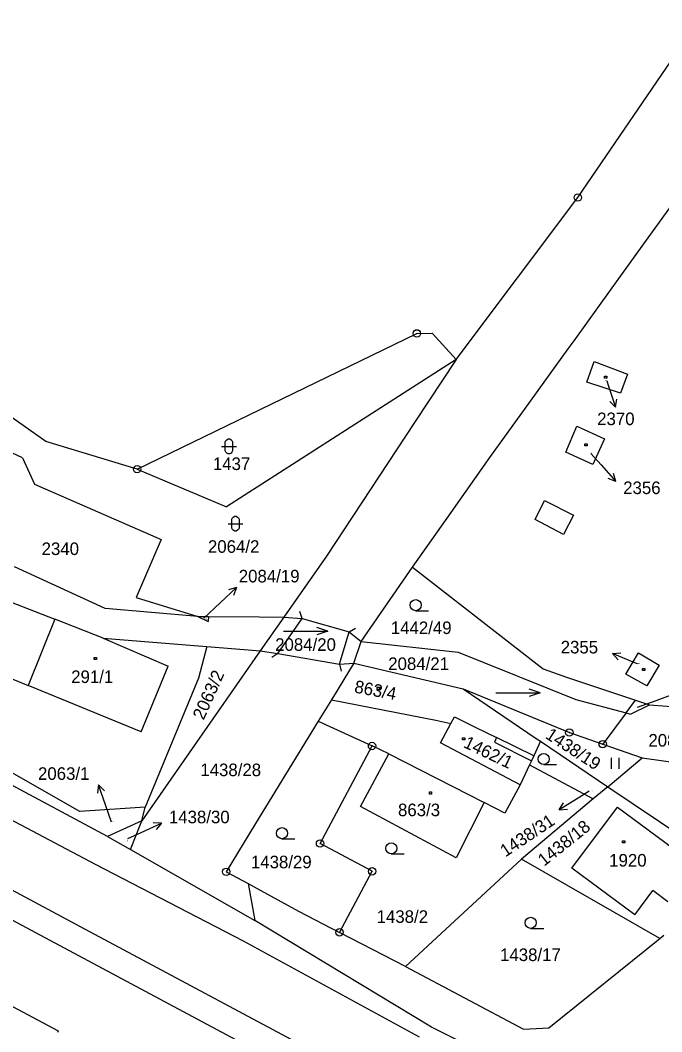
# Model space of a CAD drawing. Extents: x -795483 to -789093, y -1112258 to -1108741.
# Drawn here: x -792952.2 to -792865.5, y -1110319.8 to -1110183.1 of the extents above; entities that cross this region are included whole.
import ezdxf

# ---------------------------------------------------------------- set-up
doc = ezdxf.new("R2010")
doc.units = 0
for name, color, linetype in [('Komunikace', 7, 'Continuous'), ('Popis vodovodních řadů', 7, 'Continuous'), ('Vrstva 1', 7, 'Continuous'), ('Vrstva 14', 7, 'Continuous'), ('Vrstva 15', 7, 'Continuous'), ('Vrstva 16', 7, 'Continuous'), ('Vrstva 2', 7, 'Continuous'), ('Vrstva 23', 7, 'Continuous'), ('Vrstva 25', 7, 'Continuous'), ('Vrstva 28', 7, 'Continuous')]:
    doc.layers.add(name, color=color, linetype=linetype)

msp = doc.modelspace()

# ---------------------------------------------------------------- linework, layer by layer
at = {"layer": 'Komunikace'}
for p, q in [((-792872.92, -1110231.83), (-792872.68, -1110232.55)), ((-792875.08, -1110241.63), (-792873.69, -1110243.19)), ((-792927.41, -1110263.89), (-792925.18, -1110261.82)), ((-792868.75, -1110270.08), (-792869.36, -1110269.83)), ((-792868.77, -1110275.95), (-792866.25, -1110275.03)), ((-792875.31, -1110287.31), (-792876.79, -1110288.23)), ((-792939.88, -1110291.47), (-792940.65, -1110289.28)), ((-792937.68, -1110293.68), (-792935.87, -1110292.86))]:
    msp.add_line(p, q, dxfattribs=at)
at = {"layer": 'Popis vodovodních řadů'}
for p, q in [((-792914.11, -1110263.94), (-792914.42, -1110263)), ((-792907.75, -1110265.75), (-792906.88, -1110265.27)), ((-792917.38, -1110268.7), (-792918.22, -1110269.22)), ((-792909.08, -1110270.11), (-792908.84, -1110271.07))]:
    msp.add_line(p, q, dxfattribs=at)
at = {"layer": 'Vrstva 1'}
for p, q in [((-792876.83, -1110207.04), (-792860.5, -1110183.08)), ((-792867.33, -1110212.5), (-792861.96, -1110205.07)), ((-792893.29, -1110228.94), (-792876.83, -1110207.04)), ((-792872.43, -1110219.57), (-792867.33, -1110212.5)), ((-792877.35, -1110226.4), (-792872.43, -1110219.57)), ((-792936.43, -1110243.76), (-792898.61, -1110225.41)), ((-792898.61, -1110225.41), (-792896.52, -1110225.36)), ((-792896.52, -1110225.36), (-792893.29, -1110228.94)), ((-792878.15, -1110227.5), (-792877.35, -1110226.4)), ((-792883.23, -1110234.55), (-792878.15, -1110227.5)), ((-792893.29, -1110228.94), (-792924.34, -1110248.84)), ((-792893.29, -1110228.94), (-792898.91, -1110237.46)), ((-792875.6, -1110231.99), (-792874.62, -1110229.22)), ((-792874.62, -1110229.22), (-792870.1, -1110230.91)), ((-792870.1, -1110230.91), (-792871.07, -1110233.51)), ((-792871.07, -1110233.51), (-792875.6, -1110231.99)), ((-792888.74, -1110242.19), (-792883.23, -1110234.55)), ((-792898.91, -1110237.46), (-792910.83, -1110255.53)), ((-792878.45, -1110241.45), (-792876.98, -1110237.97)), ((-792876.98, -1110237.97), (-792873.23, -1110239.68)), ((-792951.92, -1110242.23), (-792956.62, -1110240.06)), ((-792873.23, -1110239.68), (-792874.8, -1110243.12)), ((-792874.8, -1110243.12), (-792878.45, -1110241.45)), ((-792951.92, -1110242.23), (-792950.31, -1110245.78)), ((-792893.98, -1110249.64), (-792888.74, -1110242.19)), ((-792936.43, -1110243.76), (-792924.34, -1110248.84)), ((-792950.31, -1110245.78), (-792933.18, -1110253.25)), ((-792899.17, -1110257.02), (-792893.98, -1110249.64)), ((-792933.18, -1110253.25), (-792936.55, -1110261.13)), ((-792910.83, -1110255.53), (-792916.57, -1110263.77)), ((-792940.73, -1110262.6), (-792953.02, -1110256.95)), ((-792906.12, -1110267.05), (-792899.17, -1110257.02)), ((-792899.17, -1110257.02), (-792881.53, -1110270.73)), ((-792958.2, -1110259.87), (-792947.55, -1110264.05)), ((-792936.55, -1110261.13), (-792928.23, -1110263.66)), ((-792928.23, -1110263.66), (-792940.73, -1110262.6)), ((-792928.23, -1110263.66), (-792926.8, -1110264.36)), ((-792928.23, -1110263.66), (-792926.76, -1110263.67)), ((-792926.76, -1110263.67), (-792926.8, -1110264.36)), ((-792926.76, -1110263.67), (-792919.91, -1110263.74)), ((-792919.91, -1110263.74), (-792916.57, -1110263.77)), ((-792916.57, -1110263.77), (-792919.79, -1110268.32)), ((-792916.57, -1110263.77), (-792914.11, -1110263.94)), ((-792914.11, -1110263.94), (-792907.75, -1110265.75)), ((-792947.55, -1110264.05), (-792951.18, -1110272.99)), ((-792941.03, -1110266.61), (-792947.55, -1110264.05)), ((-792941.03, -1110266.61), (-792927.02, -1110267.74)), ((-792907.75, -1110265.75), (-792906.12, -1110267.05)), ((-792927.02, -1110267.74), (-792928.14, -1110272.02)), ((-792927.02, -1110267.74), (-792921.4, -1110268.19)), ((-792907.12, -1110270), (-792906.12, -1110267.05)), ((-792906.12, -1110267.05), (-792893, -1110268.51)), ((-792961.7, -1110268.67), (-792951.18, -1110272.99)), ((-792919.79, -1110268.32), (-792935.78, -1110291.3)), ((-792921.4, -1110268.19), (-792919.79, -1110268.32)), ((-792919.79, -1110268.32), (-792917.38, -1110268.7)), ((-792917.38, -1110268.7), (-792909.08, -1110270.11)), ((-792893, -1110268.51), (-792877.11, -1110274.91)), ((-792870.36, -1110271.49), (-792868.65, -1110268.61)), ((-792868.65, -1110268.61), (-792865.84, -1110270.25)), ((-792909.08, -1110270.11), (-792907.12, -1110270)), ((-792907.12, -1110270), (-792907.69, -1110270.93)), ((-792907.12, -1110270), (-792892.36, -1110273.46)), ((-792881.53, -1110270.73), (-792878.38, -1110271.88)), ((-792865.84, -1110270.25), (-792867.49, -1110273.06)), ((-792928.14, -1110272.02), (-792935.32, -1110289.46)), ((-792907.69, -1110270.93), (-792910.16, -1110274.96)), ((-792878.38, -1110271.88), (-792869.04, -1110275)), ((-792867.49, -1110273.06), (-792870.36, -1110271.49)), ((-792892.36, -1110273.46), (-792877.98, -1110279.37)), ((-792892.36, -1110273.46), (-792882.45, -1110280.15)), ((-792877.11, -1110274.91), (-792870.31, -1110276.7)), ((-792944.19, -1110290.03), (-792968.57, -1110276.11)), ((-792910.16, -1110274.96), (-792911.93, -1110277.84)), ((-792910.16, -1110274.96), (-792896.04, -1110277.71)), ((-792870.31, -1110276.7), (-792869.04, -1110275)), ((-792869.7, -1110276.86), (-792867.13, -1110275.64)), ((-792869.04, -1110275), (-792867.13, -1110275.64)), ((-792867.13, -1110275.64), (-792832.52, -1110277.99)), ((-792894.02, -1110278.16), (-792893.53, -1110277.23)), ((-792893.53, -1110277.23), (-792890.72, -1110278.62)), ((-792870.31, -1110276.7), (-792873.47, -1110280.93)), ((-792870.31, -1110276.7), (-792869.7, -1110276.86)), ((-792940.44, -1110293.43), (-792969.24, -1110277.99)), ((-792911.93, -1110277.84), (-792920.4, -1110291.66)), ((-792911.93, -1110277.84), (-792904.66, -1110281.18)), ((-792896.04, -1110277.71), (-792894.02, -1110278.16)), ((-792895.4, -1110280.77), (-792894.02, -1110278.16)), ((-792890.72, -1110278.62), (-792887.81, -1110280.05)), ((-792882.78, -1110282.53), (-792887.81, -1110280.05)), ((-792882.45, -1110280.15), (-792881.86, -1110280.55)), ((-792877.98, -1110279.37), (-792873.47, -1110280.93)), ((-792911.69, -1110294.36), (-792904.66, -1110281.18)), ((-792902.39, -1110282.23), (-792904.66, -1110281.18)), ((-792884.61, -1110286.45), (-792895.4, -1110280.77)), ((-792881.86, -1110280.55), (-792882.78, -1110282.53)), ((-792881.86, -1110280.55), (-792872.78, -1110286.68)), ((-792873.47, -1110280.93), (-792868.13, -1110282.78)), ((-792906.21, -1110289.36), (-792902.39, -1110282.23)), ((-792882.78, -1110282.53), (-792883.08, -1110283.17)), ((-792872.78, -1110286.68), (-792868.13, -1110282.78)), ((-792868.13, -1110282.78), (-792858.5, -1110284.12)), ((-792883.35, -1110283.75), (-792884.61, -1110286.45)), ((-792883.08, -1110283.17), (-792883.35, -1110283.75)), ((-792883.35, -1110283.75), (-792874.76, -1110288.34)), ((-792987.4, -1110286.52), (-792903.63, -1110331.24)), ((-792884.61, -1110286.45), (-792886.72, -1110290.26)), ((-792872.78, -1110286.68), (-792874.76, -1110288.34)), ((-792872.78, -1110286.68), (-792855.41, -1110298.4)), ((-792874.76, -1110288.34), (-792884.46, -1110296.46)), ((-792935.32, -1110289.46), (-792944.19, -1110290.03)), ((-792935.78, -1110291.3), (-792935.32, -1110289.46)), ((-792896.99, -1110294.3), (-792906.21, -1110289.36)), ((-792889.5, -1110288.84), (-792893.29, -1110296.28)), ((-792886.72, -1110290.26), (-792889.5, -1110288.84)), ((-792877.63, -1110297.71), (-792871.48, -1110289.47)), ((-792871.48, -1110289.47), (-792863, -1110295.7)), ((-792935.78, -1110291.3), (-792940.44, -1110293.43)), ((-792937.34, -1110295.19), (-792935.78, -1110291.3)), ((-792920.4, -1110291.66), (-792924.39, -1110298.18)), ((-792940.44, -1110293.43), (-792937.34, -1110295.19)), ((-792937.34, -1110295.19), (-792920.52, -1110304.75)), ((-792904.65, -1110298.12), (-792911.69, -1110294.36)), ((-792893.29, -1110296.28), (-792896.99, -1110294.3)), ((-792884.46, -1110296.46), (-792900.15, -1110310.99)), ((-792865.76, -1110307.22), (-792884.46, -1110296.46)), ((-792924.39, -1110298.18), (-792921.42, -1110299.79)), ((-792909.06, -1110306.37), (-792904.65, -1110298.12)), ((-792869.11, -1110304.01), (-792877.63, -1110297.71)), ((-792987.23, -1110298.41), (-792947.08, -1110319.7)), ((-792921.42, -1110299.79), (-792920.21, -1110300.45)), ((-792921.42, -1110299.79), (-792920.52, -1110304.75)), ((-792920.21, -1110300.45), (-792914.61, -1110303.49)), ((-792869.11, -1110304.01), (-792866.7, -1110300.73)), ((-792864.66, -1110302.23), (-792866.7, -1110300.73)), ((-792914.61, -1110303.49), (-792909.06, -1110306.37)), ((-792896.6, -1110319.19), (-792920.52, -1110304.75)), ((-792900.15, -1110310.99), (-792909.06, -1110306.37)), ((-792880.76, -1110319.28), (-792865.76, -1110307.22)), ((-792865.76, -1110307.22), (-792865.22, -1110306.76)), ((-792900.15, -1110310.99), (-792884.2, -1110319.45)), ((-792947.08, -1110319.7), (-792947.2, -1110319.92)), ((-792892.13, -1110321.45), (-792896.6, -1110319.19)), ((-792884.2, -1110319.45), (-792880.76, -1110319.28))]:
    msp.add_line(p, q, dxfattribs=at)
msp.add_lwpolyline([(-792936.43, -1110243.76), (-792948.79, -1110240.01), (-792954.6, -1110235.91)], dxfattribs=at)
at = {"layer": 'Vrstva 16'}
for p, q in [((-792872.68, -1110232.55), (-792871.73, -1110235.4)), ((-792871.73, -1110235.4), (-792872.52, -1110234.6)), ((-792871.73, -1110235.4), (-792871.57, -1110234.29)), ((-792873.69, -1110243.19), (-792871.7, -1110245.43)), ((-792871.7, -1110245.43), (-792871.99, -1110244.35)), ((-792871.7, -1110245.43), (-792872.73, -1110245.02)), ((-792925.18, -1110261.82), (-792922.98, -1110259.77)), ((-792922.98, -1110259.77), (-792924.06, -1110260.09)), ((-792922.98, -1110259.77), (-792923.38, -1110260.82)), ((-792872.13, -1110268.67), (-792871.01, -1110268.6)), ((-792869.36, -1110269.83), (-792872.13, -1110268.67)), ((-792872.13, -1110268.67), (-792871.4, -1110269.52)), ((-792866.25, -1110275.03), (-792863.43, -1110273.99)), ((-792941.65, -1110286.45), (-792941.79, -1110287.56)), ((-792940.65, -1110289.28), (-792941.65, -1110286.45)), ((-792941.65, -1110286.45), (-792940.84, -1110287.23)), ((-792876.79, -1110288.23), (-792879.34, -1110289.82)), ((-792879.34, -1110289.82), (-792878.75, -1110288.86)), ((-792879.34, -1110289.82), (-792878.22, -1110289.71)), ((-792935.87, -1110292.86), (-792933.13, -1110291.63)), ((-792933.13, -1110291.63), (-792934.25, -1110291.58)), ((-792933.13, -1110291.63), (-792933.84, -1110292.49))]:
    msp.add_line(p, q, dxfattribs=at)
at = {"layer": 'Vrstva 2'}
for p, q in [((-792882.6, -1110250.56), (-792881.34, -1110248.01)), ((-792881.34, -1110248.01), (-792877.43, -1110250)), ((-792877.43, -1110250), (-792878.75, -1110252.61)), ((-792878.75, -1110252.61), (-792882.6, -1110250.56)), ((-792917.38, -1110268.7), (-792914.11, -1110263.94)), ((-792941.03, -1110266.61), (-792932.22, -1110270.38)), ((-792909.08, -1110270.11), (-792907.75, -1110265.75)), ((-792935.89, -1110279.29), (-792932.22, -1110270.38)), ((-792935.89, -1110279.29), (-792951.18, -1110272.99)), ((-792980.05, -1110277.11), (-792942.11, -1110297.14)), ((-792887.81, -1110280.05), (-792888.12, -1110280.67)), ((-792888.12, -1110280.67), (-792883.08, -1110283.17)), ((-792902.39, -1110282.23), (-792889.5, -1110288.84)), ((-792985.44, -1110283.55), (-792944.81, -1110305.21)), ((-792942.11, -1110297.14), (-792922.09, -1110307.54)), ((-792944.81, -1110305.21), (-792903.48, -1110327.29)), ((-792922.09, -1110307.54), (-792898.28, -1110320.5))]:
    msp.add_line(p, q, dxfattribs=at)
at = {"layer": 'Vrstva 23'}
for p, q in [((-792925.01, -1110240.68), (-792923.01, -1110240.68)), ((-792924.51, -1110240.08), (-792924.41, -1110239.88)), ((-792924.51, -1110241.28), (-792924.51, -1110240.08)), ((-792924.41, -1110239.88), (-792924.31, -1110239.78)), ((-792924.31, -1110239.78), (-792924.11, -1110239.68)), ((-792924.11, -1110239.68), (-792923.91, -1110239.68)), ((-792923.91, -1110239.68), (-792923.71, -1110239.78)), ((-792923.71, -1110239.78), (-792923.61, -1110239.88)), ((-792923.61, -1110239.88), (-792923.51, -1110240.08)), ((-792923.51, -1110240.08), (-792923.51, -1110241.28)), ((-792924.41, -1110241.48), (-792924.51, -1110241.28)), ((-792924.31, -1110241.58), (-792924.41, -1110241.48)), ((-792924.11, -1110241.68), (-792924.31, -1110241.58)), ((-792923.91, -1110241.68), (-792924.11, -1110241.68)), ((-792923.71, -1110241.58), (-792923.91, -1110241.68)), ((-792923.61, -1110241.48), (-792923.71, -1110241.58)), ((-792923.51, -1110241.28), (-792923.61, -1110241.48)), ((-792923.63, -1110250.53), (-792923.53, -1110250.33)), ((-792923.53, -1110250.33), (-792923.43, -1110250.23)), ((-792923.43, -1110250.23), (-792923.23, -1110250.13)), ((-792923.23, -1110250.13), (-792923.03, -1110250.13)), ((-792923.03, -1110250.13), (-792922.83, -1110250.23)), ((-792922.83, -1110250.23), (-792922.73, -1110250.33)), ((-792922.73, -1110250.33), (-792922.63, -1110250.53)), ((-792924.13, -1110251.13), (-792922.13, -1110251.13)), ((-792923.63, -1110251.73), (-792923.63, -1110250.53)), ((-792922.63, -1110250.53), (-792922.63, -1110251.73)), ((-792923.53, -1110251.93), (-792923.63, -1110251.73)), ((-792923.43, -1110252.03), (-792923.53, -1110251.93)), ((-792923.23, -1110252.13), (-792923.43, -1110252.03)), ((-792923.03, -1110252.13), (-792923.23, -1110252.13)), ((-792922.83, -1110252.03), (-792923.03, -1110252.13)), ((-792922.73, -1110251.93), (-792922.83, -1110252.03)), ((-792922.63, -1110251.73), (-792922.73, -1110251.93)), ((-792898.76, -1110262.89), (-792897.01, -1110262.89)), ((-792910.63, -1110265.67), (-792912.13, -1110265.17)), ((-792916.63, -1110265.67), (-792910.63, -1110265.67)), ((-792910.63, -1110265.67), (-792912.13, -1110266.17)), ((-792881.93, -1110273.99), (-792883.43, -1110273.49)), ((-792887.93, -1110273.99), (-792881.93, -1110273.99)), ((-792881.93, -1110273.99), (-792883.43, -1110274.49)), ((-792872.29, -1110284.28), (-792872.29, -1110282.78)), ((-792871.29, -1110282.78), (-792871.29, -1110284.28)), ((-792881.45, -1110283.69), (-792879.7, -1110283.69)), ((-792916.84, -1110293.72), (-792915.09, -1110293.72)), ((-792902.06, -1110295.76), (-792900.31, -1110295.76)), ((-792883.2, -1110305.83), (-792881.45, -1110305.83))]:
    msp.add_line(p, q, dxfattribs=at)
for centre in [(-792898.76, -1110262.14), (-792881.45, -1110282.94), (-792916.84, -1110292.97), (-792902.06, -1110295.01), (-792883.2, -1110305.08)]:
    msp.add_circle(centre, 0.75, dxfattribs=at)
at = {"layer": 'Vrstva 25'}
for p, q in [((-792873.21, -1110231.18), (-792872.91, -1110231.18)), ((-792873.21, -1110231.48), (-792873.21, -1110231.18)), ((-792872.91, -1110231.18), (-792872.91, -1110231.48)), ((-792872.91, -1110231.48), (-792873.21, -1110231.48)), ((-792875.89, -1110240.33), (-792875.59, -1110240.33)), ((-792875.89, -1110240.63), (-792875.89, -1110240.33)), ((-792875.59, -1110240.63), (-792875.89, -1110240.63)), ((-792875.59, -1110240.33), (-792875.59, -1110240.63)), ((-792942.22, -1110269.2), (-792941.92, -1110269.2)), ((-792942.22, -1110269.5), (-792942.22, -1110269.2)), ((-792941.92, -1110269.2), (-792941.92, -1110269.5)), ((-792941.92, -1110269.5), (-792942.22, -1110269.5)), ((-792868.08, -1110270.69), (-792867.78, -1110270.69)), ((-792868.08, -1110270.99), (-792868.08, -1110270.69)), ((-792867.78, -1110270.69), (-792867.78, -1110270.99)), ((-792867.78, -1110270.99), (-792868.08, -1110270.99)), ((-792903.95, -1110273.24), (-792903.65, -1110273.24)), ((-792903.95, -1110273.54), (-792903.95, -1110273.24)), ((-792903.65, -1110273.54), (-792903.95, -1110273.54)), ((-792903.65, -1110273.24), (-792903.65, -1110273.54)), ((-792892.41, -1110280.07), (-792892.11, -1110280.07)), ((-792892.41, -1110280.37), (-792892.41, -1110280.07)), ((-792892.11, -1110280.37), (-792892.41, -1110280.37)), ((-792892.11, -1110280.07), (-792892.11, -1110280.37)), ((-792896.9, -1110287.4), (-792896.6, -1110287.4)), ((-792896.9, -1110287.7), (-792896.9, -1110287.4)), ((-792896.6, -1110287.7), (-792896.9, -1110287.7)), ((-792896.6, -1110287.4), (-792896.6, -1110287.7)), ((-792870.77, -1110293.98), (-792870.47, -1110293.98)), ((-792870.77, -1110294.28), (-792870.77, -1110293.98)), ((-792870.47, -1110293.98), (-792870.47, -1110294.28)), ((-792870.47, -1110294.28), (-792870.77, -1110294.28))]:
    msp.add_line(p, q, dxfattribs=at)
at = {"layer": 'Vrstva 28'}
for centre, radius in [((-792876.83, -1110207.04), 0.5), ((-792876.83, -1110207.04), 0.01), ((-792898.61, -1110225.41), 0.5), ((-792898.61, -1110225.41), 0.01), ((-792936.43, -1110243.76), 0.5), ((-792936.43, -1110243.76), 0.01), ((-792877.98, -1110279.37), 0.5), ((-792877.98, -1110279.37), 0.01), ((-792904.66, -1110281.18), 0.5), ((-792904.66, -1110281.18), 0.01), ((-792873.47, -1110280.93), 0.5), ((-792873.47, -1110280.93), 0.01), ((-792911.69, -1110294.36), 0.5), ((-792911.69, -1110294.36), 0.01), ((-792924.39, -1110298.18), 0.5), ((-792924.39, -1110298.18), 0.01), ((-792904.65, -1110298.12), 0.5), ((-792904.65, -1110298.12), 0.01), ((-792909.06, -1110306.37), 0.5), ((-792909.06, -1110306.37), 0.01)]:
    msp.add_circle(centre, radius, dxfattribs=at)

# ---------------------------------------------------------------- texts
at = {"layer": 'Vrstva 14'}
for s, height, p in [('1437', 1.7, (-792926.18, -1110243.88)), ('2340', 1.7, (-792949.34, -1110255.37)), ('2064/2', 1.7, (-792926.85, -1110255.07)), ('1442/49', 1.7, (-792902.12, -1110266.05)), ('2084/20', 1.7, (-792917.76, -1110268.32)), ('2084/21', 1.7, (-792902.47, -1110270.91)), ('1442/57', 0.1, (-792869.05, -1110275.95)), ('2084/22', 1.7, (-792867.29, -1110281.26)), ('1438/28', 1.7, (-792927.88, -1110285.26)), ('1438/31', 0.1, (-792875.31, -1110287.31)), ('2063/1', 0.1, (-792939.88, -1110291.47)), ('1438/29', 1.7, (-792921.04, -1110297.71)), ('1438/2', 1.7, (-792904.04, -1110305.09)), ('1438/17', 1.7, (-792887.35, -1110310.25))]:
    msp.add_text(s, height=height, dxfattribs=at).set_placement(p)
for s, height, rotation, p in [('2084/19', 0.1, 331.3895, (-792927.41, -1110263.89)), ('2063/2', 1.7, 65.7723, (-792927.44, -1110277.77)), ('1438/19', 1.7, 326.9082, (-792881.35, -1110280.04)), ('1438/18', 1.7, 38.6959, (-792881.39, -1110297.52)), ('1438/30', 0.1, 249.1456, (-792937.68, -1110293.68))]:
    msp.add_text(s, height=height, rotation=rotation, dxfattribs=at).set_placement(p)
at = {"layer": 'Vrstva 15'}
for s, height, p in [('2370', 0.1, (-792873.1, -1110231.83)), ('2356', 0.1, (-792875.08, -1110241.63)), ('2355', 0.1, (-792868.75, -1110270.08)), ('291/1', 1.7, (-792945.34, -1110272.67)), ('863/3', 1.7, (-792901.15, -1110290.67)), ('1920', 1.7, (-792872.59, -1110297.48))]:
    msp.add_text(s, height=height, dxfattribs=at).set_placement(p)
for s, rotation, p in [('863/4', 349.3655, (-792907.14, -1110273.94)), ('1462/1', 334.3041, (-792892.42, -1110281.29))]:
    msp.add_text(s, height=1.7, rotation=rotation, dxfattribs=at).set_placement(p)
at = {"layer": 'Vrstva 16'}
for s, p in [('2370', (-792874.22, -1110237.81)), ('2356', (-792870.7, -1110247.13)), ('2084/19', (-792922.68, -1110259.07)), ('2355', (-792879.15, -1110268.67)), ('2063/1', (-792949.83, -1110285.76)), ('1438/30', (-792932.13, -1110291.63))]:
    msp.add_text(s, height=1.7, dxfattribs=at).set_placement(p)
msp.add_text('1438/31', height=1.7, rotation=33.7584, dxfattribs=at).set_placement((-792886.62, -1110296.25))

doc.saveas('drawing.dxf')
